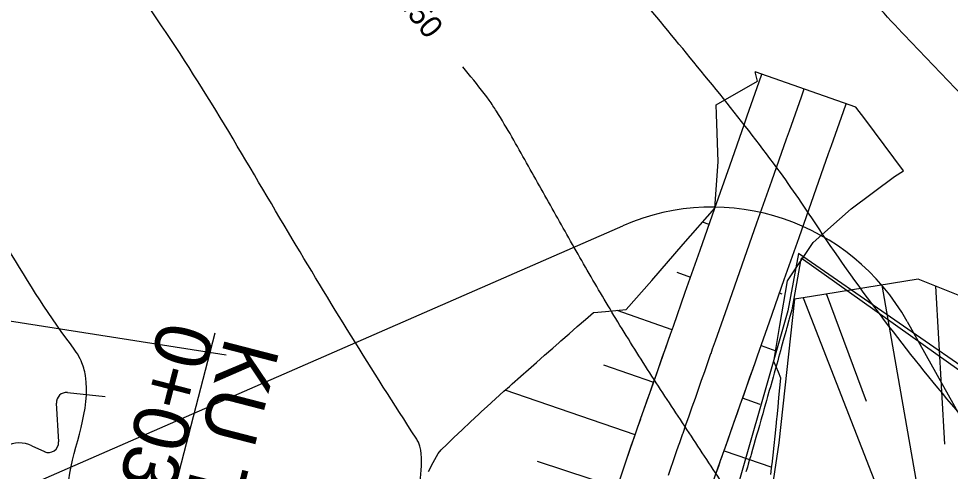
# Model space of a CAD drawing. Extents: x -564043 to -563833, y -1163561 to -1163412.
# Drawn here: x -563941.23 to -563920.35, y -1163476.4 to -1163466.24 of the extents above; entities that cross this region are included whole.
import ezdxf

# ---------------------------------------------------------------- set-up
doc = ezdxf.new("R2010")
doc.units = 0
for name, color, linetype in [('5', 7, 'Continuous'), ('_popis staničení T1', 7, 'Continuous'), ('Default', 7, 'Continuous'), ('Line', 7, 'Continuous'), ('podélný profil', 7, 'Continuous'), ('Vrstva 24', 7, 'Continuous'), ('Vrstva 25', 7, 'Continuous'), ('Vrstva 26', 7, 'Continuous')]:
    doc.layers.add(name, color=color, linetype=linetype)

msp = doc.modelspace()

# ---------------------------------------------------------------- linework, layer by layer
for points in [[(-563927.712, -1163476.432), (-563927.643, -1163476.229), (-563927.62, -1163476.16), (-563927.574, -1163476.026), (-563927.504, -1163475.823), (-563927.434, -1163475.621), (-563927.388, -1163475.491), (-563927.363, -1163475.419), (-563927.293, -1163475.22), (-563927.289, -1163475.206), (-563927.223, -1163475.02), (-563927.153, -1163474.82), (-563927.083, -1163474.621), (-563927.013, -1163474.421), (-563926.957, -1163474.263), (-563926.943, -1163474.222), (-563926.872, -1163474.022), (-563926.802, -1163473.822), (-563926.732, -1163473.623), (-563926.662, -1163473.423), (-563926.662, -1163473.422), (-563926.626, -1163473.319), (-563926.562, -1163473.139), (-563926.294, -1163472.376), (-563925.963, -1163471.432), (-563925.631, -1163470.489), (-563925.3, -1163469.545), (-563924.968, -1163468.602), (-563924.905, -1163468.421), (-563924.637, -1163467.658), (-563924.576, -1163467.486)], [(-563927.712, -1163476.432), (-563927.643, -1163476.229), (-563927.62, -1163476.16), (-563927.574, -1163476.026), (-563927.504, -1163475.823), (-563927.434, -1163475.621), (-563927.388, -1163475.491), (-563927.363, -1163475.419), (-563927.293, -1163475.22), (-563927.289, -1163475.206), (-563927.223, -1163475.02), (-563927.153, -1163474.82), (-563927.083, -1163474.621), (-563927.013, -1163474.421), (-563926.957, -1163474.263), (-563926.943, -1163474.222), (-563926.872, -1163474.022), (-563926.802, -1163473.822), (-563926.732, -1163473.623), (-563926.662, -1163473.423), (-563926.662, -1163473.422), (-563926.626, -1163473.319), (-563926.562, -1163473.139), (-563926.294, -1163472.376), (-563925.963, -1163471.432), (-563925.631, -1163470.489), (-563925.3, -1163469.545), (-563924.968, -1163468.602), (-563924.905, -1163468.421), (-563924.637, -1163467.658), (-563924.576, -1163467.486)], [(-563924.676, -1163467.645), (-563924.732, -1163467.431)], [(-563924.676, -1163467.645), (-563924.732, -1163467.431)], [(-563924.008, -1163472.119), (-563923.43, -1163471.262), (-563922.574, -1163470.503), (-563921.61, -1163469.782), (-563921.407, -1163469.65), (-563922.274, -1163468.488), (-563922.471, -1163468.226), (-563924.732, -1163467.431)], [(-563925.631, -1163470.489), (-563925.556, -1163469.455), (-563925.595, -1163468.382), (-563925.604, -1163468.176), (-563924.676, -1163467.645)], [(-563925.631, -1163470.489), (-563925.556, -1163469.455), (-563925.595, -1163468.382), (-563925.604, -1163468.176), (-563924.676, -1163467.645)], [(-563926.673, -1163476.482), (-563926.628, -1163476.35), (-563926.559, -1163476.15), (-563926.49, -1163475.95), (-563926.445, -1163475.822), (-563926.42, -1163475.751), (-563926.35, -1163475.551), (-563926.345, -1163475.538), (-563926.28, -1163475.351), (-563926.209, -1163475.152), (-563926.139, -1163474.952), (-563926.069, -1163474.753), (-563926.014, -1163474.594), (-563925.999, -1163474.553), (-563925.929, -1163474.353), (-563925.859, -1163474.154), (-563925.789, -1163473.954), (-563925.719, -1163473.755), (-563925.718, -1163473.753), (-563925.682, -1163473.651), (-563925.619, -1163473.47), (-563925.351, -1163472.707), (-563925.019, -1163471.764), (-563924.688, -1163470.82), (-563924.356, -1163469.877), (-563924.025, -1163468.933), (-563923.962, -1163468.753), (-563923.694, -1163467.99), (-563923.633, -1163467.817)], [(-563925.614, -1163476.477), (-563925.546, -1163476.28), (-563925.502, -1163476.154), (-563925.476, -1163476.082), (-563925.406, -1163475.882), (-563925.402, -1163475.869), (-563925.336, -1163475.683), (-563925.266, -1163475.483), (-563925.196, -1163475.284), (-563925.126, -1163475.084), (-563925.07, -1163474.926), (-563925.056, -1163474.884), (-563924.986, -1163474.685), (-563924.915, -1163474.485), (-563924.845, -1163474.286), (-563924.775, -1163474.086), (-563924.775, -1163474.084), (-563924.739, -1163473.982), (-563924.675, -1163473.801), (-563924.407, -1163473.039), (-563924.076, -1163472.095), (-563923.744, -1163471.152), (-563923.413, -1163470.208), (-563923.082, -1163469.265), (-563923.018, -1163469.084), (-563922.75, -1163468.321), (-563922.689, -1163468.149)], [(-563925.614, -1163476.477), (-563925.546, -1163476.28), (-563925.502, -1163476.154), (-563925.476, -1163476.082), (-563925.406, -1163475.882), (-563925.402, -1163475.869), (-563925.336, -1163475.683), (-563925.266, -1163475.483), (-563925.196, -1163475.284), (-563925.126, -1163475.084), (-563925.07, -1163474.926), (-563925.056, -1163474.884), (-563924.986, -1163474.685), (-563924.915, -1163474.485), (-563924.845, -1163474.286), (-563924.775, -1163474.086), (-563924.775, -1163474.084), (-563924.739, -1163473.982), (-563924.675, -1163473.801), (-563924.407, -1163473.039), (-563924.076, -1163472.095), (-563923.744, -1163471.152), (-563923.413, -1163470.208), (-563923.082, -1163469.265), (-563923.018, -1163469.084), (-563922.75, -1163468.321), (-563922.689, -1163468.149)], [(-563924.008, -1163472.119), (-563923.43, -1163471.262), (-563922.574, -1163470.503), (-563921.61, -1163469.782), (-563921.407, -1163469.65), (-563922.274, -1163468.488), (-563922.471, -1163468.226)], [(-563932.051, -1163476.402), (-563931.941, -1163476.2), (-563931.829, -1163475.999), (-563931.764, -1163475.913), (-563931.734, -1163475.884), (-563931.663, -1163475.815), (-563931.479, -1163475.639), (-563931.294, -1163475.463), (-563931.108, -1163475.289), (-563930.921, -1163475.115), (-563930.858, -1163475.056), (-563930.734, -1163474.942), (-563930.546, -1163474.77), (-563930.357, -1163474.6), (-563930.235, -1163474.491), (-563930.17, -1163474.433), (-563929.99, -1163474.272), (-563929.978, -1163474.262), (-563929.809, -1163474.111), (-563929.629, -1163473.951), (-563929.447, -1163473.79), (-563929.265, -1163473.63), (-563929.121, -1163473.503), (-563929.083, -1163473.47), (-563928.9, -1163473.31), (-563928.717, -1163473.15), (-563928.533, -1163472.99), (-563928.348, -1163472.831), (-563928.347, -1163472.83), (-563928.083, -1163472.807), (-563927.618, -1163472.768), (-563927.046, -1163472.112), (-563926.339, -1163471.3), (-563925.631, -1163470.489)], [(-563923.696, -1163471.61), (-563923.713, -1163471.675), (-563923.91, -1163472.772), (-563923.964, -1163472.971), (-563923.973, -1163473.003), (-563924.021, -1163473.177), (-563924.024, -1163473.19), (-563924.037, -1163473.235), (-563924.084, -1163473.408), (-563924.099, -1163473.463), (-563924.144, -1163473.626), (-563924.162, -1163473.689), (-563924.205, -1163473.844), (-563924.224, -1163473.915), (-563924.265, -1163474.063), (-563924.273, -1163474.091), (-563924.288, -1163474.143), (-563924.302, -1163474.193), (-563924.326, -1163474.281), (-563924.349, -1163474.362), (-563924.387, -1163474.498), (-563924.412, -1163474.584), (-563924.449, -1163474.716), (-563924.474, -1163474.806), (-563924.51, -1163474.934), (-563924.532, -1163475.009), (-563924.56, -1163475.107), (-563924.565, -1163475.127), (-563924.572, -1163475.152), (-563924.6, -1163475.249), (-563924.634, -1163475.369), (-563924.663, -1163475.469), (-563924.697, -1163475.587), (-563924.726, -1163475.69), (-563924.759, -1163475.804), (-563924.79, -1163475.91), (-563924.822, -1163476.021), (-563924.829, -1163476.046), (-563924.853, -1163476.129), (-563924.861, -1163476.154), (-563924.885, -1163476.239), (-563924.903, -1163476.3), (-563924.917, -1163476.348), (-563924.935, -1163476.409)], [(-563918.514, -1163475.302), (-563923.696, -1163471.61)], [(-563936.58, -1163473.788), (-563948.11, -1163471.977), (-563953.964, -1163474.44)], [(-563924.375, -1163476.469), (-563924.352, -1163476.253), (-563924.351, -1163476.238), (-563924.329, -1163476.037), (-563924.306, -1163475.82), (-563924.284, -1163475.604), (-563924.261, -1163475.388), (-563924.244, -1163475.216), (-563924.239, -1163475.171), (-563924.217, -1163474.955), (-563924.196, -1163474.738), (-563924.174, -1163474.521), (-563924.153, -1163474.305), (-563924.153, -1163474.303), (-563924.209, -1163474.168), (-563924.309, -1163473.93), (-563924.174, -1163473.121), (-563924.008, -1163472.119)], [(-563924.375, -1163476.469), (-563924.352, -1163476.253), (-563924.351, -1163476.238), (-563924.329, -1163476.037), (-563924.306, -1163475.82), (-563924.284, -1163475.604), (-563924.261, -1163475.388), (-563924.244, -1163475.216), (-563924.239, -1163475.171), (-563924.217, -1163474.955), (-563924.196, -1163474.738), (-563924.174, -1163474.521), (-563924.153, -1163474.305), (-563924.153, -1163474.303), (-563924.209, -1163474.168), (-563924.309, -1163473.93), (-563924.174, -1163473.121), (-563924.008, -1163472.119)], [(-563927.94, -1163477.121), (-563927.62, -1163476.16), (-563927.388, -1163475.491), (-563927.289, -1163475.206), (-563927.055, -1163474.541), (-563926.957, -1163474.263), (-563926.626, -1163473.319), (-563926.562, -1163473.139)], [(-563925.727, -1163476.805), (-563925.502, -1163476.154), (-563925.402, -1163475.869), (-563925.168, -1163475.204), (-563925.07, -1163474.926), (-563924.739, -1163473.982), (-563924.675, -1163473.801)]]:
    msp.add_lwpolyline(points)
msp.add_lwpolyline([(-563930.469, -1163501.126), (-563927.863, -1163499.14), (-563925.937, -1163497.674), (-563921.059, -1163495.43), (-563912.613, -1163489.681), (-563911.421, -1163482.517), (-563913.266, -1163479.715), (-563914.137, -1163478.749), (-563916.309, -1163476.467), (-563917.281, -1163475.995), (-563923.761, -1163471.506), (-563924, -1163472.797), (-563925.435, -1163477.844), (-563927.008, -1163483.992), (-563927.659, -1163487.507), (-563928.13, -1163490.05), (-563928.806, -1163493.379), (-563930.34, -1163499.841), (-563930.622, -1163501.15)], close=True)
at = {"layer": '5'}
for p, q in [((-563952.243, -1163481.627), (-563927.696, -1163470.887)), ((-563921.324, -1163473.035), (-563903.913, -1163504.291))]:
    msp.add_line(p, q, dxfattribs=at)
msp.add_arc((-563925.692, -1163475.468), 5, 29.1194, 113.6313, dxfattribs=at)
at = {"layer": '_popis staničení T1'}
msp.add_lwpolyline([(-563940.586, -1163487.812), (-563936.832, -1163473.29)], dxfattribs=at)
at = {"layer": 'Default'}
msp.add_lwpolyline([(-563917.567, -1163473.488), (-563921.074, -1163472.087), (-563923.466, -1163472.472), (-563923.844, -1163472.533), (-563924.198, -1163475.76), (-563924.511, -1163477.861), (-563924.518, -1163477.902), (-563924.828, -1163479.981), (-563924.849, -1163480.121), (-563924.856, -1163480.165), (-563924.906, -1163480.403), (-563924.984, -1163480.77), (-563924.987, -1163480.784), (-563925.501, -1163483.223), (-563925.543, -1163483.419), (-563925.776, -1163484.521), (-563925.948, -1163485.244), (-563926.867, -1163489.1)], dxfattribs=at)
at = {"layer": 'Line'}
for p, q in [((-563925.762, -1163470.86), (-563925.91, -1163470.808)), ((-563926.485, -1163471.931), (-563926.176, -1163472.039)), ((-563921.893, -1163472.219), (-563920.362, -1163480.924)), ((-563920.479, -1163475.786), (-563920.684, -1163472.243)), ((-563924.122, -1163472.418), (-563924.182, -1163472.397)), ((-563923.655, -1163472.502), (-563920.364, -1163480.938)), ((-563922.236, -1163474.829), (-563923.127, -1163472.417)), ((-563926.59, -1163473.219), (-563927.824, -1163472.785)), ((-563924.596, -1163473.576), (-563924.269, -1163473.691)), ((-563928.125, -1163474.005), (-563927.004, -1163474.398)), ((-563927.417, -1163475.578), (-563930.327, -1163474.573)), ((-563924.618, -1163474.893), (-563925.01, -1163474.756)), ((-563925.424, -1163475.935), (-563924.358, -1163476.306)), ((-563929.614, -1163476.166), (-563927.821, -1163476.761))]:
    msp.add_line(p, q, dxfattribs=at)
at = {"layer": 'podélný profil'}
for points in [[(-563940.139, -1163474.63), (-563939.292, -1163474.714)], [(-563940.335, -1163475.736), (-563940.387, -1163474.868)], [(-563940.935, -1163475.823), (-563940.656, -1163475.954)]]:
    msp.add_lwpolyline(points, dxfattribs=at)
for centre, radius, start, end in [((-563940.161, -1163474.854), 0.226, 84.2679, 183.3851), ((-563941.222, -1163476.436), 0.677, 64.8623, 116.5568), ((-563940.561, -1163475.749), 0.226, 244.8644, 3.4114)]:
    msp.add_arc(centre, radius, start, end, dxfattribs=at)
at = {"layer": 'Vrstva 24'}
for points in [[(-563919.378, -1163476.01), (-563920.124, -1163475.135), (-563923.224, -1163471.065), (-563923.696, -1163470.358), (-563924.164, -1163469.694), (-563926.769, -1163466.405), (-563928.095, -1163464.779), (-563929.404, -1163463.14), (-563932.31, -1163459.338), (-563933.826, -1163457.042), (-563935.107, -1163454.848), (-563938.341, -1163449.378), (-563939.751, -1163446.922), (-563941.145, -1163444.457), (-563942.639, -1163441.761)], [(-563941.26, -1163493.011), (-563939.004, -1163490.701), (-563935.168, -1163486.585), (-563933.596, -1163484.774), (-563933.04, -1163483.789), (-563932.447, -1163481.939), (-563932.386, -1163481.578), (-563932.335, -1163479.091), (-563932.359, -1163478.881), (-563932.37, -1163478.699), (-563932.356, -1163477.982), (-563932.286, -1163477.265), (-563932.226, -1163476.548), (-563932.242, -1163475.831), (-563932.273, -1163475.745), (-563932.328, -1163475.651), (-563935.188, -1163471.035), (-563938.348, -1163465.934), (-563938.454, -1163465.786), (-563938.858, -1163465.285), (-563944.231, -1163458.582)]]:
    msp.add_spline(points, degree=3, dxfattribs=at)
at = {"layer": 'Vrstva 26'}
for points in [[(-563903.213, -1163473.112), (-563903.335, -1163473.037), (-563904.668, -1163472.172), (-563906.499, -1163470.852), (-563910.711, -1163467.339), (-563913.027, -1163465.278), (-563914.752, -1163463.594), (-563917.784, -1163460.234), (-563919.818, -1163457.596), (-563921.06, -1163455.802), (-563922.391, -1163453.664), (-563923.256, -1163452.127), (-563925.571, -1163447.916), (-563926.722, -1163445.846), (-563927.87, -1163443.819), (-563929.217, -1163441.493)], [(-563945.261, -1163485.579), (-563942.429, -1163481.606), (-563942.364, -1163481.506), (-563941.862, -1163480.718), (-563941.1, -1163479.337), (-563940.179, -1163477.031), (-563940.14, -1163476.815), (-563940.109, -1163476.584), (-563939.736, -1163474.248), (-563939.829, -1163473.919), (-563940.073, -1163473.538), (-563942.893, -1163468.839), (-563943.521, -1163467.678), (-563944.104, -1163466.494), (-563944.685, -1163465.307), (-563945.306, -1163464.14), (-563945.974, -1163463.136), (-563948.418, -1163460.207), (-563952.009, -1163455.848), (-563952.987, -1163454.388), (-563953.586, -1163453.328), (-563954.161, -1163452.255), (-563954.736, -1163451.183), (-563955.25, -1163450.271)], [(-563905.617, -1163487.172), (-563905.709, -1163486.429), (-563906.139, -1163484.405), (-563906.329, -1163483.595), (-563906.621, -1163482.767), (-563906.829, -1163482.378), (-563907.081, -1163482.014), (-563907.56, -1163481.452), (-563908.067, -1163480.924), (-563908.726, -1163480.275), (-563912.103, -1163476.606), (-563915.337, -1163473.082), (-563915.91, -1163472.421), (-563916.763, -1163471.467), (-563918.06, -1163470.074), (-563919.378, -1163468.702), (-563920.698, -1163467.331), (-563922.003, -1163465.944), (-563924.219, -1163463.46), (-563925.291, -1163462.186), (-563926.342, -1163460.894), (-563927.353, -1163459.538), (-563928.172, -1163458.338), (-563930.361, -1163454.824), (-563930.463, -1163454.637)], [(-563938.486, -1163500.528), (-563938.463, -1163500.513), (-563937.665, -1163500.022), (-563936.97, -1163499.566), (-563930.777, -1163494.949), (-563928.884, -1163493.45), (-563928.656, -1163493.192), (-563928.195, -1163492.447), (-563924.372, -1163485.735), (-563923.788, -1163484.5), (-563923.604, -1163483.639), (-563923.611, -1163481.604), (-563923.712, -1163481.017), (-563924.518, -1163478.475), (-563924.689, -1163477.919), (-563924.751, -1163477.798), (-563925.518, -1163476.583), (-563926.306, -1163475.384), (-563927.092, -1163474.184), (-563927.851, -1163472.968), (-563928.532, -1163471.813), (-563929.192, -1163470.645), (-563929.849, -1163469.476), (-563930.525, -1163468.317), (-563930.688, -1163468.07), (-563931.156, -1163467.471), (-563931.276, -1163467.321)]]:
    msp.add_spline(points, degree=3, dxfattribs=at)

# ---------------------------------------------------------------- texts
at = {"layer": '_popis staničení T1'}
for s, p in [('0+038.64', (-563938.042, -1163472.977)), ('KU T1 ', (-563936.59, -1163473.352))]:
    msp.add_text(s, height=1.25, rotation=255.5058, dxfattribs=at).set_placement(p)
at = {"layer": 'Vrstva 25'}
msp.add_text('327.50', height=0.5, rotation=308.6467, dxfattribs=at).set_placement((-563933.352, -1163465.125))

doc.saveas('drawing.dxf')
